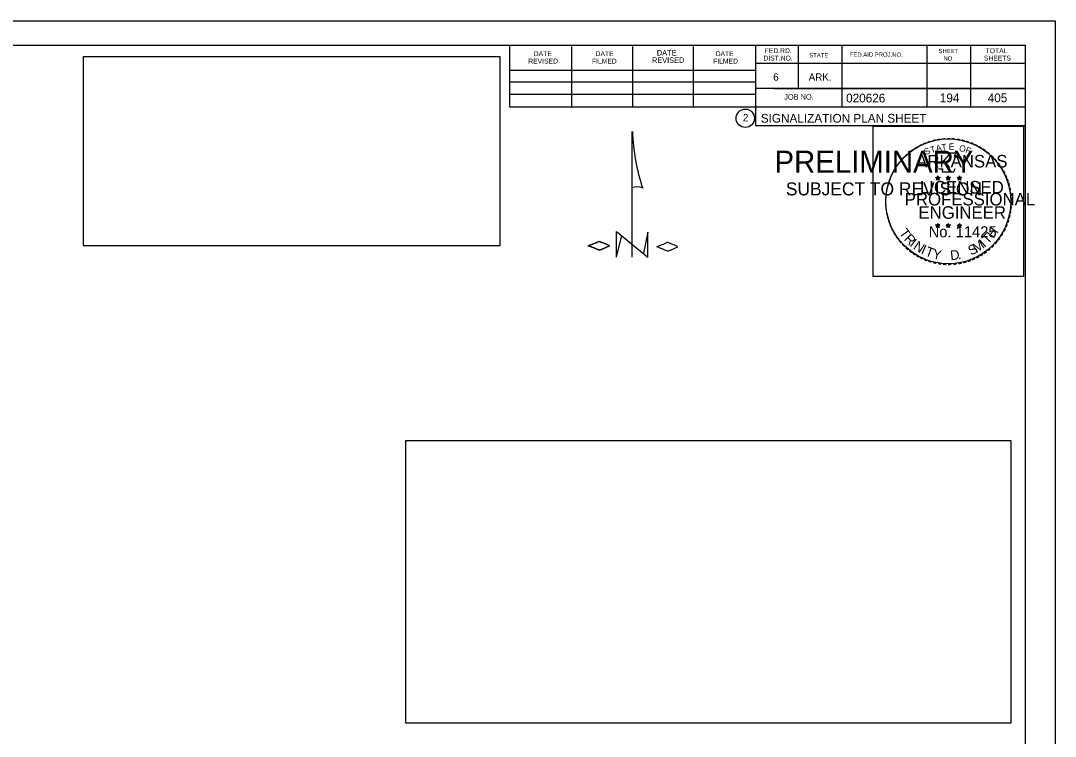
# Model space of a CAD drawing. Extents: x 1280123 to 1281123, y 1892664 to 1893304.
# Drawn here: x 1280627.5 to 1281122.7, y 1892961.7 to 1893304 of the extents above; entities that cross this region are included whole.
import ezdxf

# ---------------------------------------------------------------- set-up
doc = ezdxf.new("R2010")
doc.units = 0
for name, color, linetype in [('R_Border', 7, 'Continuous'), ('R_Border PE', 7, 'Continuous'), ('R_Border Prem', 7, 'Continuous'), ('R_No Plot', 7, 'Continuous'), ('T_Drafting', 7, 'Continuous')]:
    doc.layers.add(name, color=color, linetype=linetype)

msp = doc.modelspace()

# ---------------------------------------------------------------- linework, layer by layer
at = {"layer": 'R_Border'}
for p, q in [((1280159.93, 1893292.35), (1281108.47, 1893292.35)), ((1280861.69, 1893262.71), (1280861.69, 1893292.35)), ((1280891.27, 1893262.71), (1280891.27, 1893291.75)), ((1280920.55, 1893262.71), (1280920.55, 1893291.75)), ((1280949.59, 1893262.71), (1280949.59, 1893291.75)), ((1280979.17, 1893292.35), (1280979.17, 1893253.95)), ((1280999.69, 1893292.35), (1280999.69, 1893271.53)), ((1281020.51, 1893292.35), (1281020.51, 1893262.71)), ((1281061.25, 1893292.35), (1281061.25, 1893262.71)), ((1281082.07, 1893292.35), (1281082.07, 1893262.71)), ((1281108.47, 1892675.97), (1281108.47, 1893292.35)), ((1281108.47, 1893283.53), (1280979.17, 1893283.53)), ((1281108.47, 1893283.59), (1281108.47, 1893283.59)), ((1280861.69, 1893280.29), (1280979.17, 1893280.29)), ((1280861.69, 1893274.71), (1280979.17, 1893274.71)), ((1280861.69, 1893262.71), (1280861.69, 1893268.89)), ((1280861.69, 1893268.89), (1280979.17, 1893268.89)), ((1281108.47, 1893271.53), (1280979.17, 1893271.53)), ((1280988.05, 1893271.53), (1281108.47, 1893271.53)), ((1281108.47, 1893262.71), (1280861.69, 1893262.71)), ((1280979.17, 1893253.95), (1281108.47, 1893253.95))]:
    msp.add_line(p, q, dxfattribs=at)
msp.add_circle((1280974.33, 1893257.35), 4.4, dxfattribs=at)
at = {"layer": 'R_Border PE'}
for p, q in [((1281065.45, 1893229.03), (1281066.5, 1893228.7)), ((1281065.45, 1893229.03), (1281066.21, 1893228.89)), ((1281065.45, 1893229.03), (1281066.16, 1893228.66)), ((1281065.85, 1893227.8), (1281066.5, 1893228.7)), ((1281065.85, 1893227.8), (1281066.23, 1893228.54)), ((1281065.85, 1893227.8), (1281066.49, 1893228.46)), ((1281066.5, 1893229.79), (1281066.37, 1893229.03)), ((1281067.14, 1893227.8), (1281066.49, 1893228.45)), ((1281066.5, 1893228.7), (1281066.5, 1893229.79)), ((1281066.5, 1893229.79), (1281066.64, 1893229.04)), ((1281067.54, 1893229.03), (1281066.5, 1893228.7)), ((1281067.14, 1893227.8), (1281066.5, 1893228.7)), ((1281067.54, 1893229.03), (1281066.68, 1893228.88)), ((1281067.14, 1893227.8), (1281066.72, 1893228.68)), ((1281067.54, 1893229.03), (1281066.93, 1893228.72)), ((1281070.46, 1893229.03), (1281071.51, 1893228.7)), ((1281070.46, 1893229.03), (1281071.22, 1893228.89)), ((1281070.46, 1893229.03), (1281071.17, 1893228.66)), ((1281070.86, 1893227.8), (1281071.51, 1893228.7)), ((1281070.86, 1893227.8), (1281071.24, 1893228.54)), ((1281070.86, 1893227.8), (1281071.5, 1893228.46)), ((1281071.51, 1893229.79), (1281071.38, 1893229.03)), ((1281072.15, 1893227.8), (1281071.5, 1893228.45)), ((1281071.51, 1893228.7), (1281071.51, 1893229.79)), ((1281071.51, 1893229.79), (1281071.65, 1893229.04)), ((1281072.55, 1893229.03), (1281071.51, 1893228.7)), ((1281072.15, 1893227.8), (1281071.51, 1893228.7)), ((1281072.55, 1893229.03), (1281071.69, 1893228.88)), ((1281072.15, 1893227.8), (1281071.73, 1893228.68)), ((1281072.55, 1893229.03), (1281071.94, 1893228.72)), ((1281075.75, 1893228.99), (1281076.8, 1893228.66)), ((1281075.75, 1893228.99), (1281076.51, 1893228.86)), ((1281075.75, 1893228.99), (1281076.46, 1893228.63)), ((1281076.15, 1893227.77), (1281076.8, 1893228.66)), ((1281076.15, 1893227.77), (1281076.53, 1893228.5)), ((1281076.15, 1893227.77), (1281076.79, 1893228.42)), ((1281076.8, 1893229.75), (1281076.68, 1893229)), ((1281077.44, 1893227.77), (1281076.79, 1893228.41)), ((1281076.8, 1893228.66), (1281076.8, 1893229.75)), ((1281076.8, 1893229.75), (1281076.95, 1893229)), ((1281077.84, 1893228.99), (1281076.8, 1893228.66)), ((1281077.44, 1893227.77), (1281076.8, 1893228.66)), ((1281077.84, 1893228.99), (1281076.98, 1893228.85)), ((1281077.44, 1893227.77), (1281077.03, 1893228.64)), ((1281077.84, 1893228.99), (1281077.23, 1893228.69)), ((1281065.44, 1893206.31), (1281066.48, 1893205.98)), ((1281065.44, 1893206.31), (1281066.2, 1893206.17)), ((1281065.44, 1893206.31), (1281066.15, 1893205.94)), ((1281065.84, 1893205.09), (1281066.48, 1893205.98)), ((1281065.84, 1893205.09), (1281066.21, 1893205.82)), ((1281065.84, 1893205.09), (1281066.48, 1893205.74)), ((1281066.48, 1893207.07), (1281066.36, 1893206.32)), ((1281066.48, 1893205.98), (1281066.48, 1893207.07)), ((1281066.48, 1893207.07), (1281066.63, 1893206.32)), ((1281067.53, 1893206.31), (1281066.48, 1893205.98)), ((1281067.12, 1893205.09), (1281066.48, 1893205.98)), ((1281067.12, 1893205.09), (1281066.48, 1893205.73)), ((1281067.53, 1893206.31), (1281066.67, 1893206.16)), ((1281067.12, 1893205.09), (1281066.71, 1893205.96)), ((1281067.53, 1893206.31), (1281066.91, 1893206)), ((1281070.44, 1893206.31), (1281071.49, 1893205.98)), ((1281070.44, 1893206.31), (1281071.2, 1893206.17)), ((1281070.44, 1893206.31), (1281071.16, 1893205.94)), ((1281070.84, 1893205.09), (1281071.49, 1893205.98)), ((1281070.84, 1893205.09), (1281071.22, 1893205.82)), ((1281070.84, 1893205.09), (1281071.49, 1893205.74)), ((1281071.49, 1893207.07), (1281071.37, 1893206.32)), ((1281071.49, 1893205.98), (1281071.49, 1893207.07)), ((1281071.49, 1893207.07), (1281071.64, 1893206.32)), ((1281072.53, 1893206.31), (1281071.49, 1893205.98)), ((1281072.13, 1893205.09), (1281071.49, 1893205.98)), ((1281072.13, 1893205.09), (1281071.49, 1893205.73)), ((1281072.53, 1893206.31), (1281071.67, 1893206.16)), ((1281072.13, 1893205.09), (1281071.72, 1893205.96)), ((1281072.53, 1893206.31), (1281071.92, 1893206)), ((1281075.75, 1893206.28), (1281076.79, 1893205.95)), ((1281075.75, 1893206.28), (1281076.5, 1893206.14)), ((1281075.75, 1893206.28), (1281076.46, 1893205.91)), ((1281076.14, 1893205.06), (1281076.79, 1893205.95)), ((1281076.14, 1893205.06), (1281076.52, 1893205.79)), ((1281076.14, 1893205.06), (1281076.79, 1893205.71)), ((1281076.79, 1893207.04), (1281076.67, 1893206.29)), ((1281076.79, 1893205.95), (1281076.79, 1893207.04)), ((1281076.79, 1893207.04), (1281076.94, 1893206.29)), ((1281077.83, 1893206.28), (1281076.79, 1893205.95)), ((1281077.43, 1893205.06), (1281076.79, 1893205.95)), ((1281077.43, 1893205.06), (1281076.79, 1893205.7)), ((1281077.83, 1893206.28), (1281076.98, 1893206.13)), ((1281077.43, 1893205.06), (1281077.02, 1893205.93)), ((1281077.83, 1893206.28), (1281077.22, 1893205.97))]:
    msp.add_line(p, q, dxfattribs=at)
for points in [[(1281065.57, 1893240.66), (1281066.38, 1893238.18)], [(1281076.11, 1893237.9), (1281076.53, 1893238.75), (1281074.48, 1893238.68), (1281074.92, 1893240.66), (1281065.57, 1893240.66)], [(1281067.05, 1893233.39), (1281067.05, 1893233.13), (1281068.74, 1893233.08), (1281068.58, 1893231.66), (1281074.19, 1893231.66), (1281074.79, 1893233.26)], [(1281066.5, 1893229.79), (1281067.14, 1893227.8), (1281065.45, 1893229.03), (1281067.54, 1893229.03), (1281065.85, 1893227.8), (1281066.5, 1893229.79)], [(1281071.51, 1893229.79), (1281072.15, 1893227.8), (1281070.46, 1893229.03), (1281072.55, 1893229.03), (1281070.86, 1893227.8), (1281071.51, 1893229.79)], [(1281076.8, 1893229.75), (1281077.44, 1893227.77), (1281075.75, 1893228.99), (1281077.84, 1893228.99), (1281076.15, 1893227.77), (1281076.8, 1893229.75)], [(1281066.48, 1893207.07), (1281067.12, 1893205.09), (1281065.44, 1893206.31), (1281067.53, 1893206.31), (1281065.84, 1893205.09), (1281066.48, 1893207.07)], [(1281071.49, 1893207.07), (1281072.13, 1893205.09), (1281070.44, 1893206.31), (1281072.53, 1893206.31), (1281070.84, 1893205.09), (1281071.49, 1893207.07)], [(1281076.79, 1893207.04), (1281077.43, 1893205.06), (1281075.75, 1893206.28), (1281077.83, 1893206.28), (1281076.14, 1893205.06), (1281076.79, 1893207.04)]]:
    msp.add_lwpolyline(points, dxfattribs=at)
for centre, radius in [((1281066.49, 1893228.69), 0.517), ((1281066.49, 1893228.69), 0.434), ((1281066.49, 1893228.69), 0.347), ((1281066.49, 1893228.69), 0.297), ((1281066.49, 1893228.69), 0.224), ((1281066.49, 1893228.69), 0.149), ((1281066.49, 1893228.69), 0.0889), ((1281071.5, 1893228.69), 0.517), ((1281071.5, 1893228.69), 0.434), ((1281071.5, 1893228.69), 0.347), ((1281071.5, 1893228.69), 0.297), ((1281071.5, 1893228.69), 0.224), ((1281071.5, 1893228.69), 0.149), ((1281071.5, 1893228.69), 0.0889), ((1281076.8, 1893228.66), 0.517), ((1281076.8, 1893228.66), 0.434), ((1281076.8, 1893228.66), 0.347), ((1281076.8, 1893228.66), 0.297), ((1281076.8, 1893228.66), 0.224), ((1281076.8, 1893228.66), 0.149), ((1281076.8, 1893228.66), 0.0889), ((1281066.48, 1893205.97), 0.517), ((1281066.48, 1893205.97), 0.434), ((1281066.48, 1893205.97), 0.347), ((1281066.48, 1893205.97), 0.297), ((1281066.48, 1893205.97), 0.224), ((1281066.48, 1893205.97), 0.149), ((1281066.48, 1893205.97), 0.0889), ((1281071.49, 1893205.97), 0.517), ((1281071.49, 1893205.97), 0.434), ((1281071.49, 1893205.97), 0.347), ((1281071.49, 1893205.97), 0.297), ((1281071.49, 1893205.97), 0.224), ((1281071.49, 1893205.97), 0.149), ((1281071.49, 1893205.97), 0.0889), ((1281076.79, 1893205.94), 0.517), ((1281076.79, 1893205.94), 0.434), ((1281076.79, 1893205.94), 0.347), ((1281076.79, 1893205.94), 0.297), ((1281076.79, 1893205.94), 0.224), ((1281076.79, 1893205.94), 0.149), ((1281076.79, 1893205.94), 0.0889)]:
    msp.add_circle(centre, radius, dxfattribs=at)
at = {"layer": 'R_No Plot'}
for p, q in [((1280122.72, 1893304.03), (1281122.72, 1893304.03)), ((1281035.3, 1893184.9), (1281035.3, 1893184.9))]:
    msp.add_line(p, q, dxfattribs=at)
for points in [[(1280122.7, 1893304.03), (1281122.72, 1893304.03), (1281122.72, 1892664.02), (1280122.7, 1892664.02)], [(1281035.53, 1893253.58), (1281107.53, 1893253.58), (1281107.53, 1893181.58), (1281035.53, 1893181.58)]]:
    msp.add_lwpolyline(points, close=True, dxfattribs=at)
msp.add_circle((1281071.53, 1893217.58), 29.86, dxfattribs=at)
at = {"layer": 'T_Drafting'}
for p, q in [((1280920.23, 1893190.97), (1280920.23, 1893250.95)), ((1280912.73, 1893190.97), (1280912.73, 1893203.16)), ((1280912.73, 1893203.16), (1280927.73, 1893190.97)), ((1280912.73, 1893190.99), (1280915.19, 1893201.03)), ((1280927.73, 1893202.93), (1280925.6, 1893192.74)), ((1280927.72, 1893202.92), (1280927.73, 1893202.93)), ((1280927.73, 1893190.97), (1280927.73, 1893202.93))]:
    msp.add_line(p, q, dxfattribs=at)
for points in [[(1280657.41, 1893196.55), (1280857.07, 1893196.55), (1280857.07, 1893286.82), (1280657.41, 1893286.82)], [(1280811.74, 1892968.06), (1281101.67, 1892968.06), (1281101.67, 1893103.05), (1280811.74, 1893103.05)]]:
    msp.add_lwpolyline(points, close=True, dxfattribs=at)
for centre, radius, start, end in [((1281018.03, 1893254.88), 97.82, 182.2815, 198.4669), ((1280922.59, 1893219.02), 5.53, 61.6986, 115.682), ((1280834.68, 1893360.34), 176.2, 291.4742, 293.2539), ((1280834.91, 1893360.34), 176.2, 291.4742, 293.2539), ((1280875.99, 1893124.78), 78.93, 65.1071, 68.9839), ((1280876.22, 1893124.78), 78.93, 65.1071, 68.9839), ((1280834.68, 1893032.35), 176.2, 66.7461, 68.5258), ((1280834.91, 1893032.35), 176.2, 66.7461, 68.5258), ((1280875.99, 1893267.91), 78.93, 291.0161, 294.8929), ((1280876.22, 1893267.91), 78.93, 291.0161, 294.8929), ((1280867.53, 1893359.88), 176.2, 291.4742, 293.2539), ((1280867.53, 1893031.89), 176.2, 66.7461, 68.5258), ((1280908.85, 1893124.32), 78.93, 65.1071, 68.9839), ((1280908.85, 1893267.45), 78.93, 291.0161, 294.8929)]:
    msp.add_arc(centre, radius, start, end, dxfattribs=at)

# ---------------------------------------------------------------- texts
at = {"layer": 'R_Border'}
for s, height, p in [('DATE', 2.346, (1280873.09, 1893287.07)), ('DATE', 2.346, (1280902.67, 1893287.07)), ('DATE', 2.638, (1280932.01, 1893287.37)), ('DATE', 2.346, (1280960.15, 1893287.07)), ('FED.RD.', 2.346, (1280983.61, 1893288.51)), ('STATE', 2.052, (1281004.97, 1893286.47)), ('FED.AID PROJ.NO.', 2.052, (1281024.35, 1893286.77)), ('SHEET', 2.052, (1281066.83, 1893288.51)), ('TOTAL', 2.346, (1281089.39, 1893288.51)), ('REVISED', 2.346, (1280870.45, 1893283.53)), ('FILMED', 2.346, (1280900.93, 1893283.53)), ('REVISED', 2.638, (1280929.67, 1893283.83)), ('FILMED', 2.346, (1280958.95, 1893283.53)), ('DIST.NO.', 2.346, (1280983.01, 1893284.97)), ('NO.', 2.052, (1281069.17, 1893284.97)), ('SHEETS', 2.346, (1281088.55, 1893284.97)), ('6', 3.52, (1280987.69, 1893275.31)), ('ARK.', 3.517, (1281004.67, 1893275.31)), ('JOB NO.', 2.638, (1280992.97, 1893266.25)), ('020626', 4.2, (1281022.6, 1893264.92)), ('194', 4.2, (1281067.44, 1893265.02)), ('405', 4.2, (1281090.37, 1893265.02)), ('2', 3.52, (1280973.18, 1893255.89)), ('SIGNALIZATION PLAN SHEET', 4.2, (1280981.76, 1893255.24))]:
    msp.add_text(s, height=height, dxfattribs=at).set_placement(p)
at = {"layer": 'R_Border PE'}
for s, height, rotation, p in [('-', 4.8, 5.8968, (1281068.29, 1893245.58)), ('-', 4.8, 0.1862, (1281070.6, 1893245.8)), ('-', 4.8, 357.743, (1281072.77, 1893245.76)), ('-', 4.8, 34.0636, (1281056.22, 1893241.18)), ('-', 4.8, 28.7918, (1281058.02, 1893242.29)), ('-', 4.8, 24.3072, (1281059.91, 1893243.24)), ('S', 3, 21.594, (1281060.64, 1893239.7)), ('-', 4.8, 19.1761, (1281061.82, 1893244.04)), ('T', 3, 16.4036, (1281063.38, 1893240.69)), ('-', 4.8, 13.6302, (1281064.07, 1893244.77)), ('A', 3, 11.2132, (1281065.86, 1893241.44)), ('-', 4.8, 10.2193, (1281066.1, 1893245.25)), ('T', 3, 6.0228, (1281068.4, 1893241.94)), ('E', 3, 0.8323, (1281071.72, 1893242.27)), ('-', 4.8, 352.1617, (1281075, 1893245.59)), ('O', 3, 350.4515, (1281076.53, 1893241.64)), ('-', 4.8, 347.2049, (1281077.16, 1893245.25)), ('F', 3, 340.0707, (1281079.39, 1893240.96)), ('-', 4.8, 342.3362, (1281079.07, 1893244.78)), ('-', 4.8, 337.8551, (1281081.27, 1893244.12)), ('-', 4.8, 334.1211, (1281083.16, 1893243.3)), ('-', 4.8, 329.6409, (1281084.9, 1893242.45)), ('-', 4.8, 325.8627, (1281086.83, 1893241.37)), ('-', 4.8, 48.4231, (1281050.42, 1893236.17)), ('-', 4.8, 42.9622, (1281051.76, 1893237.61)), ('-', 4.8, 38.9507, (1281053.06, 1893238.86)), ('-', 4.8, 36.2317, (1281054.49, 1893239.99)), ('-', 4.8, 320.5297, (1281088.66, 1893240.09)), ('-', 4.8, 315.5786, (1281090.46, 1893238.63)), ('-', 4.8, 309.8797, (1281092.16, 1893236.98)), ('-', 4.8, 58.0706, (1281047, 1893231.43)), ('-', 4.8, 54.2325, (1281047.97, 1893233.01)), ('-', 4.8, 50.6142, (1281049.21, 1893234.71)), ('-', 4.8, 306.6522, (1281093.74, 1893235.17)), ('-', 4.2, 303.6753, (1281095.2, 1893233.47)), ('-', 4.8, 72.3945, (1281044.62, 1893225.87)), ('-', 4.8, 67.7743, (1281045.28, 1893227.76)), ('-', 4.8, 62.8713, (1281046.06, 1893229.59)), ('-', 4.8, 299.6684, (1281096.15, 1893231.65)), ('-', 4.8, 294.6628, (1281097.13, 1893229.81)), ('-', 4.8, 290.5728, (1281097.9, 1893228.08)), ('-', 4.8, 81.2013, (1281043.64, 1893221.59)), ('-', 4.8, 75.461, (1281044.03, 1893223.72)), ('-', 4.8, 285.1233, (1281098.6, 1893226.34)), ('-', 4.8, 280.5493, (1281099.2, 1893224.11)), ('-', 4.8, 89.0622, (1281043.33, 1893217.41)), ('-', 4.8, 85.1863, (1281043.41, 1893219.51)), ('-', 4.8, 276.5962, (1281099.69, 1893221.81)), ('-', 4.8, 274.3301, (1281099.87, 1893219.64)), ('-', 4.8, 94.1959, (1281043.44, 1893215.23)), ('-', 4.8, 98.9479, (1281043.65, 1893213.23)), ('-', 4.8, 260.9953, (1281099.7, 1893213.79)), ('-', 4.8, 263.5172, (1281099.91, 1893215.75)), ('-', 4.8, 269.9407, (1281099.97, 1893217.75)), ('-', 4.8, 101.7149, (1281044.06, 1893211.03)), ('-', 4.8, 105.4578, (1281044.55, 1893209.25)), ('-', 4.8, 109.0874, (1281045.19, 1893207.36)), ('-', 4.8, 252.8681, (1281098.82, 1893209.59)), ('-', 4.8, 255.7626, (1281099.37, 1893211.75)), ('-', 4.8, 114.0643, (1281045.95, 1893205.57)), ('-', 4.8, 115.7289, (1281046.87, 1893203.71)), ('T', 4.62, 306.0406, (1281047.76, 1893202.49)), ('H', 4.62, 54.6088, (1281093.12, 1893199.6)), ('-', 4.8, 244.6197, (1281097.37, 1893205.69)), ('-', 4.8, 247.8887, (1281098.16, 1893207.58)), ('-', 4.8, 120.4471, (1281047.94, 1893201.96)), ('-', 4.8, 125.8934, (1281049.15, 1893200.27)), ('-', 4.8, 130.7181, (1281050.53, 1893198.62)), ('R', 4.62, 314.005, (1281050.05, 1893199.35)), ('I', 4.62, 321.9694, (1281052.75, 1893196.55)), ('N', 4.62, 326.5002, (1281054.45, 1893195.14)), ('M', 4.62, 32.6563, (1281084.92, 1893192.79)), ('I', 4.62, 42.1136, (1281088.77, 1893195.34)), ('T', 4.62, 46.6444, (1281090.46, 1893196.77)), ('-', 4.8, 231.2538, (1281093.69, 1893199.78)), ('-', 4.8, 233.8452, (1281094.98, 1893201.47)), ('-', 4.8, 239.0712, (1281096.19, 1893203.43)), ('-', 4.8, 134.2238, (1281052.08, 1893196.98)), ('-', 4.8, 138.9338, (1281053.66, 1893195.59)), ('-', 4.8, 144.6463, (1281055.33, 1893194.37)), ('I', 4.62, 335.3603, (1281058.08, 1893192.78)), ('T', 4.62, 339.8912, (1281060.06, 1893191.8)), ('Y', 4.62, 347.8556, (1281063.71, 1893190.46)), ('D', 4.62, 6.3969, (1281072.67, 1893189.38)), ('S', 4.62, 26.9312, (1281082.4, 1893191.58)), ('-', 4.8, 215.7363, (1281089.04, 1893195.14)), ('-', 4.8, 221.0851, (1281090.69, 1893196.56)), ('-', 4.8, 225.7653, (1281092.25, 1893198.08)), ('-', 4.8, 148.0898, (1281057.01, 1893193.26)), ('-', 4.8, 151.5704, (1281058.75, 1893192.28)), ('-', 4.8, 154.6002, (1281060.31, 1893191.54)), ('-', 4.8, 158.5612, (1281062.19, 1893190.78)), ('-', 4.8, 162.7983, (1281064.25, 1893190.14)), ('-', 4.8, 167.5555, (1281066.39, 1893189.65)), ('.', 4.62, 13.7642, (1281076.24, 1893189.77)), ('-', 4.8, 195.4743, (1281080.01, 1893190.44)), ('-', 4.8, 200.7184, (1281082.04, 1893191.17)), ('-', 4.8, 204.2516, (1281083.89, 1893191.98)), ('-', 4.8, 207.3568, (1281085.77, 1893192.94)), ('-', 4.8, 212.2491, (1281087.44, 1893193.98)), ('-', 4.8, 173.1155, (1281068.71, 1893189.32)), ('-', 4.8, 176.5183, (1281070.95, 1893189.16)), ('-', 4.8, 181.5918, (1281073.18, 1893189.22)), ('-', 4.8, 185.8167, (1281075.61, 1893189.45)), ('-', 4.8, 191.2858, (1281077.82, 1893189.84))]:
    msp.add_text(s, height=height, rotation=rotation, dxfattribs=at).set_placement(p)
for s, height, p in [('ARKANSAS', 6, (1281056.13, 1893233.8)), ('DWB', 0.03, (1281066.46, 1893228.68)), ('DWB', 0.03, (1281071.47, 1893228.68)), ('DWB', 0.03, (1281076.76, 1893228.65)), ('LICENSED', 6, (1281057.92, 1893221.35)), ('PROFESSIONAL', 6, (1281050.65, 1893215.64)), ('ENGINEER', 6, (1281057.21, 1893209.26)), ('No. 11425', 5.271, (1281062.1, 1893200.41)), ('DWB', 0.03, (1281066.45, 1893205.96)), ('DWB', 0.03, (1281071.45, 1893205.96)), ('DWB', 0.03, (1281076.75, 1893205.93))]:
    msp.add_text(s, height=height, dxfattribs=at).set_placement(p)
at = {"layer": 'R_Border Prem'}
for s, height, p in [('PRELIMINARY', 10.5, (1280988.32, 1893231.34)), ('SUBJECT TO REVISION', 6.2253, (1280993.75, 1893220.45))]:
    msp.add_text(s, height=height, dxfattribs=at).set_placement(p)

doc.saveas('drawing.dxf')
